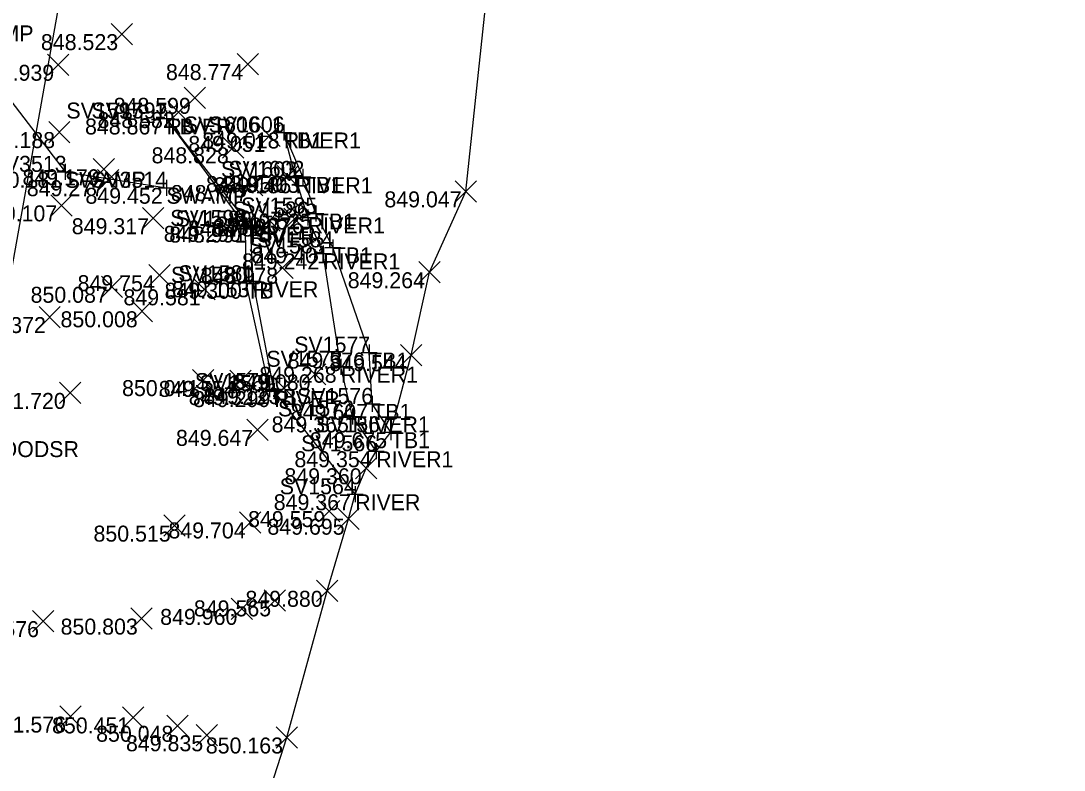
# Model space of a CAD drawing. Extents: x 2228183 to 2230895, y 679226 to 682223.
# Drawn here: x 2228343.2 to 2228408.5, y 680434.6 to 680481.5 of the extents above; entities that cross this region are included whole.
import ezdxf

# ---------------------------------------------------------------- set-up
doc = ezdxf.new("R2010")
doc.units = 0
for name, color, linetype in [('HY_X_Water_Edge', 7, 'Continuous'), ('SC_Scratch1', 7, 'Continuous'), ('SV_P_Control_Cells_Set', 7, 'Continuous'), ('SV_X_Random_Point', 7, 'Continuous'), ('SV_X_Shot_Marker', 7, 'Continuous'), ('SV_X_Terrain_Boundary', 7, 'Continuous'), ('SV_X_Text_Comment', 7, 'Continuous'), ('SV_X_Top_of_Bank', 7, 'Continuous'), ('VG_X_Tree_Line_Rt', 7, 'Continuous')]:
    doc.layers.add(name, color=color, linetype=linetype)

msp = doc.modelspace()

# ---------------------------------------------------------------- linework, layer by layer
at = {"layer": 'HY_X_Water_Edge'}
for points in [[(2228388.587, 680538.705), (2228381.654, 680540.428), (2228373.267, 680534.114), (2228362.534, 680538.041), (2228352.058, 680544.515), (2228344.28, 680554.272), (2228336.684, 680545.185), (2228336.291, 680530.248), (2228335.4, 680519.473), (2228335.533, 680511.573), (2228332.556, 680502.567), (2228338.972, 680492.245), (2228338.927, 680481.209), (2228345.953, 680472.044), (2228352.301, 680471.046)], [(2228364.112, 680451.859), (2228359.051, 680458.318), (2228357.723, 680465.192), (2228357.556, 680468.617), (2228352.299, 680475.383)], [(2228365.433, 680454.55), (2228363.954, 680456.734), (2228363.218, 680459.841), (2228362.108, 680466.937), (2228361.147, 680469.188), (2228360.378, 680471.701), (2228359.644, 680474.507)]]:
    msp.add_lwpolyline(points, dxfattribs=at)
at = {"layer": 'SV_X_Random_Point'}
for p, q in [((2228348.84, 680479.997), (2228350.174, 680481.332)), ((2228348.84, 680481.332), (2228350.174, 680479.997)), ((2228344.857, 680478.08), (2228346.191, 680479.415)), ((2228344.857, 680479.415), (2228346.191, 680478.08)), ((2228356.724, 680478.122), (2228358.058, 680479.457)), ((2228356.724, 680479.457), (2228358.058, 680478.122)), ((2228353.413, 680476.009), (2228354.747, 680477.344)), ((2228353.413, 680477.344), (2228354.747, 680476.009)), ((2228352.392, 680475.12), (2228353.726, 680476.455)), ((2228352.392, 680476.455), (2228353.726, 680475.12)), ((2228344.928, 680473.867), (2228346.262, 680475.202)), ((2228344.928, 680475.202), (2228346.262, 680473.867)), ((2228358.083, 680473.626), (2228359.417, 680474.961)), ((2228358.083, 680474.961), (2228359.417, 680473.626)), ((2228355.801, 680472.91), (2228357.135, 680474.245)), ((2228355.801, 680474.245), (2228357.135, 680472.91)), ((2228347.706, 680471.536), (2228349.04, 680472.871)), ((2228347.706, 680472.871), (2228349.04, 680471.536)), ((2228347.988, 680470.853), (2228349.322, 680472.188)), ((2228347.988, 680472.188), (2228349.322, 680470.853)), ((2228359.223, 680471.11), (2228360.557, 680472.445)), ((2228359.223, 680472.445), (2228360.557, 680471.11)), ((2228357.007, 680470.549), (2228358.341, 680471.884)), ((2228357.007, 680471.884), (2228358.341, 680470.549)), ((2228370.372, 680470.154), (2228371.706, 680471.489)), ((2228370.372, 680471.489), (2228371.706, 680470.154)), ((2228345.057, 680469.277), (2228346.391, 680470.612)), ((2228345.057, 680470.612), (2228346.391, 680469.277)), ((2228350.802, 680468.473), (2228352.136, 680469.808)), ((2228350.802, 680469.808), (2228352.136, 680468.473)), ((2228358.092, 680468.328), (2228359.426, 680469.663)), ((2228358.092, 680469.663), (2228359.426, 680468.328)), ((2228359.652, 680468.439), (2228360.986, 680469.774)), ((2228359.652, 680469.774), (2228360.986, 680468.439)), ((2228351.192, 680464.908), (2228352.526, 680466.243)), ((2228351.192, 680466.243), (2228352.526, 680464.908)), ((2228358.89, 680465.37), (2228360.224, 680466.705)), ((2228358.89, 680466.705), (2228360.224, 680465.37)), ((2228368.104, 680465.09), (2228369.438, 680466.425)), ((2228368.104, 680466.425), (2228369.438, 680465.09)), ((2228348.224, 680464.181), (2228349.558, 680465.516)), ((2228348.224, 680465.516), (2228349.558, 680464.181)), ((2228354.023, 680464.021), (2228355.357, 680465.356)), ((2228354.023, 680465.356), (2228355.357, 680464.021)), ((2228344.323, 680462.285), (2228345.657, 680463.62)), ((2228344.323, 680463.62), (2228345.657, 680462.285)), ((2228350.102, 680462.645), (2228351.436, 680463.98)), ((2228350.102, 680463.98), (2228351.436, 680462.645)), ((2228366.957, 680459.902), (2228368.291, 680461.237)), ((2228366.957, 680461.237), (2228368.291, 680459.902)), ((2228360.935, 680458.7), (2228362.269, 680460.035)), ((2228360.935, 680460.035), (2228362.269, 680458.7)), ((2228353.936, 680458.338), (2228355.27, 680459.673)), ((2228353.936, 680459.673), (2228355.27, 680458.338)), ((2228356.273, 680458.288), (2228357.607, 680459.623)), ((2228356.273, 680459.623), (2228357.607, 680458.288)), ((2228359.005, 680457.834), (2228360.339, 680459.169)), ((2228359.005, 680459.169), (2228360.339, 680457.834)), ((2228345.609, 680457.535), (2228346.943, 680458.87)), ((2228345.609, 680458.87), (2228346.943, 680457.535)), ((2228357.325, 680455.222), (2228358.659, 680456.557)), ((2228357.325, 680456.557), (2228358.659, 680455.222)), ((2228364.132, 680452.818), (2228365.466, 680454.153)), ((2228364.132, 680454.153), (2228365.466, 680452.818)), ((2228361.827, 680450.138), (2228363.161, 680451.473)), ((2228361.827, 680451.473), (2228363.161, 680450.138)), ((2228352.136, 680449.228), (2228353.47, 680450.563)), ((2228352.136, 680450.563), (2228353.47, 680449.228)), ((2228356.879, 680449.427), (2228358.213, 680450.762)), ((2228356.879, 680450.762), (2228358.213, 680449.427)), ((2228363.022, 680449.661), (2228364.356, 680450.996)), ((2228363.022, 680450.996), (2228364.356, 680449.661)), ((2228361.693, 680445.147), (2228363.027, 680446.482)), ((2228361.693, 680446.482), (2228363.027, 680445.147)), ((2228356.354, 680444.015), (2228357.688, 680445.35)), ((2228356.354, 680445.35), (2228357.688, 680444.015)), ((2228358.421, 680444.549), (2228359.755, 680445.884)), ((2228358.421, 680445.884), (2228359.755, 680444.549)), ((2228350.07, 680443.407), (2228351.404, 680444.742)), ((2228350.07, 680444.742), (2228351.404, 680443.407)), ((2228343.921, 680443.248), (2228345.255, 680444.583)), ((2228343.921, 680444.583), (2228345.255, 680443.248)), ((2228345.621, 680437.275), (2228346.955, 680438.61)), ((2228345.621, 680438.61), (2228346.955, 680437.275)), ((2228349.552, 680437.222), (2228350.886, 680438.557)), ((2228349.552, 680438.557), (2228350.886, 680437.222)), ((2228352.331, 680436.7), (2228353.665, 680438.035)), ((2228352.331, 680438.035), (2228353.665, 680436.7)), ((2228354.169, 680436.102), (2228355.503, 680437.437)), ((2228354.169, 680437.437), (2228355.503, 680436.102)), ((2228359.161, 680435.964), (2228360.495, 680437.299)), ((2228359.161, 680437.299), (2228360.495, 680435.964))]:
    msp.add_line(p, q, dxfattribs=at)
at = {"layer": 'SV_X_Shot_Marker'}
for p, q in [((2228351.799, 680475.383), (2228352.799, 680475.383)), ((2228351.799, 680475.383), (2228352.799, 680475.383)), ((2228352.299, 680475.883), (2228352.299, 680474.883)), ((2228352.299, 680475.883), (2228352.299, 680474.883)), ((2228352.299, 680475.383), (2228352.299, 680475.383)), ((2228352.299, 680475.383), (2228352.299, 680475.383)), ((2228359.644, 680475.007), (2228359.644, 680474.007)), ((2228359.644, 680475.007), (2228359.644, 680474.007)), ((2228359.144, 680474.507), (2228360.144, 680474.507)), ((2228359.144, 680474.507), (2228360.144, 680474.507)), ((2228359.644, 680474.507), (2228359.644, 680474.507)), ((2228359.644, 680474.507), (2228359.644, 680474.507)), ((2228345.953, 680472.544), (2228345.953, 680471.544)), ((2228360.378, 680472.201), (2228360.378, 680471.201)), ((2228360.847, 680472.229), (2228360.847, 680471.229)), ((2228345.453, 680472.044), (2228346.453, 680472.044)), ((2228345.953, 680472.044), (2228345.953, 680472.044)), ((2228352.301, 680471.546), (2228352.301, 680470.546)), ((2228359.878, 680471.701), (2228360.878, 680471.701)), ((2228360.347, 680471.729), (2228361.347, 680471.729)), ((2228360.378, 680471.701), (2228360.378, 680471.701)), ((2228360.847, 680471.729), (2228360.847, 680471.729)), ((2228351.801, 680471.046), (2228352.801, 680471.046)), ((2228352.301, 680471.046), (2228352.301, 680471.046)), ((2228361.147, 680469.688), (2228361.147, 680468.688)), ((2228361.648, 680469.935), (2228361.648, 680468.935)), ((2228357.244, 680469.162), (2228357.244, 680468.162)), ((2228357.556, 680469.117), (2228357.556, 680468.117)), ((2228360.647, 680469.188), (2228361.647, 680469.188)), ((2228361.147, 680469.188), (2228361.147, 680469.188)), ((2228361.148, 680469.435), (2228362.148, 680469.435)), ((2228361.648, 680469.435), (2228361.648, 680469.435)), ((2228356.744, 680468.662), (2228357.744, 680468.662)), ((2228357.056, 680468.617), (2228358.056, 680468.617)), ((2228357.244, 680468.662), (2228357.244, 680468.662)), ((2228357.556, 680468.617), (2228357.556, 680468.617)), ((2228362.712, 680467.818), (2228362.712, 680466.818)), ((2228361.608, 680466.937), (2228362.608, 680466.937)), ((2228362.108, 680467.437), (2228362.108, 680466.437)), ((2228362.108, 680466.937), (2228362.108, 680466.937)), ((2228362.212, 680467.318), (2228363.212, 680467.318)), ((2228362.712, 680467.318), (2228362.712, 680467.318)), ((2228357.295, 680465.603), (2228357.295, 680464.603)), ((2228357.723, 680465.692), (2228357.723, 680464.692)), ((2228356.795, 680465.103), (2228357.795, 680465.103)), ((2228357.223, 680465.192), (2228358.223, 680465.192)), ((2228357.295, 680465.103), (2228357.295, 680465.103)), ((2228357.723, 680465.192), (2228357.723, 680465.192)), ((2228364.993, 680461.229), (2228364.993, 680460.229)), ((2228363.218, 680460.341), (2228363.218, 680459.341)), ((2228364.493, 680460.729), (2228365.493, 680460.729)), ((2228364.993, 680460.729), (2228364.993, 680460.729)), ((2228362.718, 680459.841), (2228363.718, 680459.841)), ((2228363.218, 680459.841), (2228363.218, 680459.841)), ((2228358.26, 680458.445), (2228359.26, 680458.445)), ((2228358.76, 680458.945), (2228358.76, 680457.945)), ((2228358.76, 680458.445), (2228358.76, 680458.445)), ((2228359.051, 680458.818), (2228359.051, 680457.818)), ((2228358.551, 680458.318), (2228359.551, 680458.318)), ((2228359.051, 680458.318), (2228359.051, 680458.318)), ((2228365.181, 680458.016), (2228365.181, 680457.016)), ((2228363.954, 680457.234), (2228363.954, 680456.234)), ((2228364.681, 680457.516), (2228365.681, 680457.516)), ((2228365.181, 680457.516), (2228365.181, 680457.516)), ((2228363.454, 680456.734), (2228364.454, 680456.734)), ((2228363.954, 680456.734), (2228363.954, 680456.734)), ((2228366.349, 680456.242), (2228366.349, 680455.242)), ((2228365.849, 680455.742), (2228366.849, 680455.742)), ((2228366.349, 680455.742), (2228366.349, 680455.742)), ((2228364.933, 680454.55), (2228365.933, 680454.55)), ((2228365.433, 680455.05), (2228365.433, 680454.05)), ((2228365.433, 680454.55), (2228365.433, 680454.55)), ((2228363.612, 680451.859), (2228364.612, 680451.859)), ((2228364.112, 680452.359), (2228364.112, 680451.359)), ((2228364.112, 680451.859), (2228364.112, 680451.859))]:
    msp.add_line(p, q, dxfattribs=at)
at = {"layer": 'SV_X_Terrain_Boundary'}
msp.add_lwpolyline([(2228358.075, 680431.186), (2228359.828, 680436.631), (2228362.36, 680445.814), (2228363.689, 680450.328), (2228364.112, 680451.859), (2228364.799, 680453.485), (2228365.433, 680454.55), (2228366.349, 680455.742), (2228367.624, 680460.569), (2228368.771, 680465.757), (2228371.039, 680470.821), (2228373.269, 680491.813), (2228376.294, 680512.277), (2228380.627, 680522.966), (2228380.208, 680529.569)], dxfattribs=at)
at = {"layer": 'SV_X_Top_of_Bank'}
for points in [[(2228358.76, 680458.445), (2228357.295, 680465.103), (2228357.244, 680468.662), (2228352.299, 680475.383)], [(2228366.349, 680455.742), (2228365.181, 680457.516), (2228364.993, 680460.729), (2228362.712, 680467.318), (2228361.648, 680469.435), (2228360.847, 680471.729), (2228359.644, 680474.507)]]:
    msp.add_lwpolyline(points, dxfattribs=at)
at = {"layer": 'VG_X_Tree_Line_Rt'}
msp.add_lwpolyline([(2228410.452, 680773.345), (2228402.142, 680728.483), (2228403.602, 680691.208), (2228374.606, 680596.133), (2228370.969, 680582.119), (2228367.614, 680567.008), (2228346.3, 680486.661), (2228340.655, 680455.186), (2228334.048, 680383.235)], dxfattribs=at)

# ---------------------------------------------------------------- texts
at = {"layer": 'SC_Scratch1'}
for s, p in [('848.523', (2228344.443, 680479.664)), ('848.939', (2228340.44, 680477.747)), ('848.774', (2228352.269, 680477.789)), ('848.599', (2228348.996, 680475.676)), ('848.867', (2228347.203, 680474.383)), ('848.867', (2228347.203, 680474.383)), ('848.582', (2228347.986, 680474.787)), ('849.188', (2228340.495, 680473.534)), ('849.051', (2228353.668, 680473.293)), ('849.018', (2228354.544, 680473.507)), ('849.018', (2228354.544, 680473.507)), ('848.828', (2228351.368, 680472.577)), ('849.179', (2228343.289, 680471.203)), ('850.181', (2228340.871, 680471.044)), ('849.277', (2228343.559, 680470.52)), ('848.950', (2228354.776, 680470.777)), ('849.186', (2228355.274, 680470.701)), ('849.403', (2228355.783, 680470.729)), ('849.452', (2228347.228, 680470.046)), ('848.777', (2228352.578, 680470.216)), ('849.047', (2228365.943, 680469.821)), ('850.107', (2228340.628, 680468.944)), ('849.317', (2228346.373, 680468.14)), ('848.780', (2228353.645, 680467.995)), ('848.837', (2228355.223, 680468.106)), ('849.076', (2228356.043, 680468.188)), ('849.525', (2228356.578, 680468.435)), ('849.290', (2228352.13, 680467.662)), ('848.991', (2228352.474, 680467.617)), ('849.242', (2228357.035, 680465.937)), ('849.401', (2228357.63, 680466.318)), ('849.754', (2228346.737, 680464.575)), ('848.978', (2228354.457, 680465.037)), ('849.264', (2228363.649, 680464.757)), ('849.300', (2228352.181, 680464.103)), ('849.153', (2228352.659, 680464.192)), ('850.087', (2228343.795, 680463.848)), ('849.581', (2228349.608, 680463.688)), ('851.372', (2228339.917, 680461.952)), ('850.008', (2228345.669, 680462.312)), ('849.576', (2228359.889, 680459.729)), ('849.544', (2228362.502, 680459.569)), ('849.268', (2228358.118, 680458.841)), ('849.080', (2228356.488, 680458.367)), ('850.041', (2228349.521, 680458.005)), ('849.554', (2228351.818, 680457.955)), ('849.323', (2228353.696, 680457.445)), ('849.123', (2228354.608, 680457.501)), ('851.720', (2228341.162, 680457.202)), ('849.299', (2228353.967, 680457.318)), ('849.607', (2228360.085, 680456.516)), ('849.365', (2228358.884, 680455.734)), ('849.647', (2228352.896, 680454.889)), ('849.675', (2228361.279, 680454.742)), ('849.354', (2228360.311, 680453.55)), ('849.360', (2228359.685, 680452.485)), ('849.367', (2228359.016, 680450.859)), ('849.559', (2228357.41, 680449.805)), ('850.515', (2228347.733, 680448.895)), ('849.704', (2228352.424, 680449.094)), ('849.695', (2228358.619, 680449.328)), ('849.880', (2228357.246, 680444.814)), ('849.960', (2228351.907, 680443.682)), ('849.565', (2228354.018, 680444.216)), ('850.803', (2228345.673, 680443.074)), ('852.576', (2228339.484, 680442.915)), ('851.576', (2228341.184, 680436.942)), ('850.451', (2228345.137, 680436.889)), ('850.048', (2228347.898, 680436.367)), ('849.835', (2228349.766, 680435.769)), ('850.163', (2228354.764, 680435.631))]:
    msp.add_text(s, height=1, dxfattribs=at).set_placement(p)
at = {"layer": 'SV_P_Control_Cells_Set'}
for s, p in [('SV1597_1', (2228346.036, 680475.383)), ('SV1597', (2228347.605, 680475.383)), ('SV1606_1', (2228353.381, 680474.507)), ('SV1606', (2228354.942, 680474.507)), ('SV3513', (2228341.291, 680472.044)), ('SV1602', (2228356.176, 680471.729)), ('SV1603', (2228355.716, 680471.701)), ('SV3514', (2228347.581, 680471.046)), ('SV1586', (2228356.445, 680469.188)), ('SV1585', (2228356.979, 680469.435)), ('SV1590', (2228352.532, 680468.662)), ('SV1589', (2228352.874, 680468.617)), ('SV1584', (2228357.992, 680467.318)), ('SV1583', (2228357.446, 680466.937)), ('SV1580', (2228352.583, 680465.103)), ('SV1581', (2228353.043, 680465.192)), ('SV1577', (2228360.299, 680460.729)), ('SV1573', (2228358.556, 680459.841)), ('SV1579', (2228354.078, 680458.445)), ('SV1569', (2228354.369, 680458.318)), ('SV1576', (2228360.479, 680457.516)), ('SV1572', (2228359.283, 680456.734)), ('SV1567', (2228361.655, 680455.742)), ('SV1566', (2228360.731, 680454.55)), ('SV1564', (2228359.392, 680451.859))]:
    msp.add_text(s, height=1, dxfattribs=at).set_placement(p)
at = {"layer": 'SV_X_Text_Comment'}
for s, p in [('SWAMP', (2228338.927, 680480.209)), ('TB', (2228352.299, 680474.383)), ('RIVER', (2228352.299, 680474.383)), ('TB1', (2228359.644, 680473.507)), ('RIVER1', (2228359.644, 680473.507)), ('SWAMP', (2228345.953, 680471.044)), ('RIVER1', (2228360.378, 680470.701)), ('TB1', (2228360.847, 680470.729)), ('SWAMP', (2228352.301, 680470.046)), ('RIVER1', (2228361.147, 680468.188)), ('TB1', (2228361.648, 680468.435)), ('TB', (2228357.244, 680467.662)), ('RIVER', (2228357.556, 680467.617)), ('RIVER1', (2228362.108, 680465.937)), ('TB1', (2228362.712, 680466.318)), ('TB', (2228357.295, 680464.103)), ('RIVER', (2228357.723, 680464.192)), ('TB1', (2228364.993, 680459.729)), ('RIVER1', (2228363.218, 680458.841)), ('TB', (2228358.76, 680457.445)), ('RIVER', (2228359.051, 680457.318)), ('TB1', (2228365.181, 680456.516)), ('RIVER1', (2228363.954, 680455.734)), ('WOODSR', (2228340.655, 680454.186)), ('TB1', (2228366.349, 680454.742)), ('RIVER1', (2228365.433, 680453.55)), ('RIVER', (2228364.112, 680450.859))]:
    msp.add_text(s, height=1, dxfattribs=at).set_placement(p)

doc.saveas('drawing.dxf')
